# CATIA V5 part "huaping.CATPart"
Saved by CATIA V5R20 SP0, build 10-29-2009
Part number: 花瓶
Material "DS Light Blue": density 7860 kg/m3, Young's modulus 2e+11 Pa, Poisson ratio 0.266
Bounding box of the stored display mesh (mm): x -34.969 to 34.969, y -34.969 to 46.421, z 0 to 104.276
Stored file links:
  D:\CATIAR20\part\huaping.CATPart
  D:\CATIAR20\win_b64\startup\materials\Catalog.CATMaterial
  D:\CATIAR20\win_b64\startup\materials\blue_env_512x512.jpg
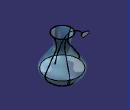
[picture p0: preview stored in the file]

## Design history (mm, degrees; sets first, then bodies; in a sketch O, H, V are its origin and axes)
Body1 (main body), material "DS Light Blue"
  Plane1: type Offset, RefPlane xy-plane, Offset 20
  Plane2: type Offset, RefPlane Plane1, Offset 20
  Plane3: type Offset, RefPlane Plane2, Offset 20
  Plane4: type Offset, RefPlane Plane3, Offset 20
  Sketch1 on Plane4, origin (0, 0, 80), H (1, 0, 0), V (0, 1, 0)
    circle A1 centre (0, 0) radius 18
    radius A1 = 18
  Sketch2 on Plane3, origin (0, 0, 60), H (1, 0, 0), V (0, 1, 0)
    circle A1 centre (0, 0) radius 12
    radius A1 = 12
  Sketch3 on Plane2, origin (0, 0, 40), H (1, 0, 0), V (0, 1, 0)
    circle A1 centre (0, 0) radius 24
    radius A1 = 24
  Sketch4 on Plane1, origin (0, 0, 20), H (1, 0, 0), V (0, 1, 0)
    circle A1 centre (0, 0) radius 35
    radius A1 = 35
  Sketch5 on xy-plane, origin (0, 0, 0), H (1, 0, 0), V (0, 1, 0)
    circle A1 centre (0, 0) radius 20
    radius A1 = 20
  Loft1: solid, Sections (Sketch1; Sketch2; Sketch3; Sketch4; Sketch5)
  Shell1: IntOffset 1, ExtOffset 0, Face face of Loft1
Body2
  Sketch6 on yz-plane, origin (0, 0, 0), H (0, 1, 0), V (0, 0, 1)
    axis line L1 (0, 101.094) -> (0, -35.2708)
    point P1 (0, 101.094)
    point P3 (0, 17.9705)
    line L2 (0, 17.9705) -> (32.3909, 17.9705)
    arc A1 centre (0.2379, 29.1375) radius 34.037 from (32.3909, 17.9705) to (19.5872, 1.1353) cw
    line L3 (19.5872, 1.1353) -> (0, 1.1353)
    point P7 (0, 1.1353)
    coincidence: P1 V, P3 L1, P7 L1
    vertical: L1 V
    horizontal: L2 H, L3 H
  Shaft1: profile Sketch6, axis Sketch6.L1, angle 360
Body3
  Sketch7 on yz-plane, origin (0, 0, 0), H (0, 1, 0), V (0, 0, 1)
    spline S1 through (-15.6659, 11.9922) (3.4698, 70.47) (27.3894, 96.8496) (45.4212, 100.1701)
  Plane5: type OffsetPt, RefPlane zx-plane, RefPoint vertex of Sketch7
  Sketch8 on Plane5, origin (0, 45.4212, 0), H (-1, 0, 0), V (0, 0, 1)
    circle A1 centre (0, 100.1701) radius 0.5
    point P1 (0, 100.1701)
    radius A1 = 0.5
    coincidence: P1 V
  Rib1: profile Sketch8, centre curve Sketch7
Body4
  Sketch9 on Plane5, origin (0, 45.4212, 0), H (-1, 0, 0), V (0, 0, 1)
    spline S1 through (-3.6702, 96.0002) (-6.9254, 103.3432) (7.5872, 101.3035) (-3.6702, 96.0002)
    point P1 (-3.6702, 96.0002)
    point P2 (-3.6702, 96.0002)
    coincidence: P1 P2
  Pad1: profile Sketch9, direction (0, 1, 0), length 1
